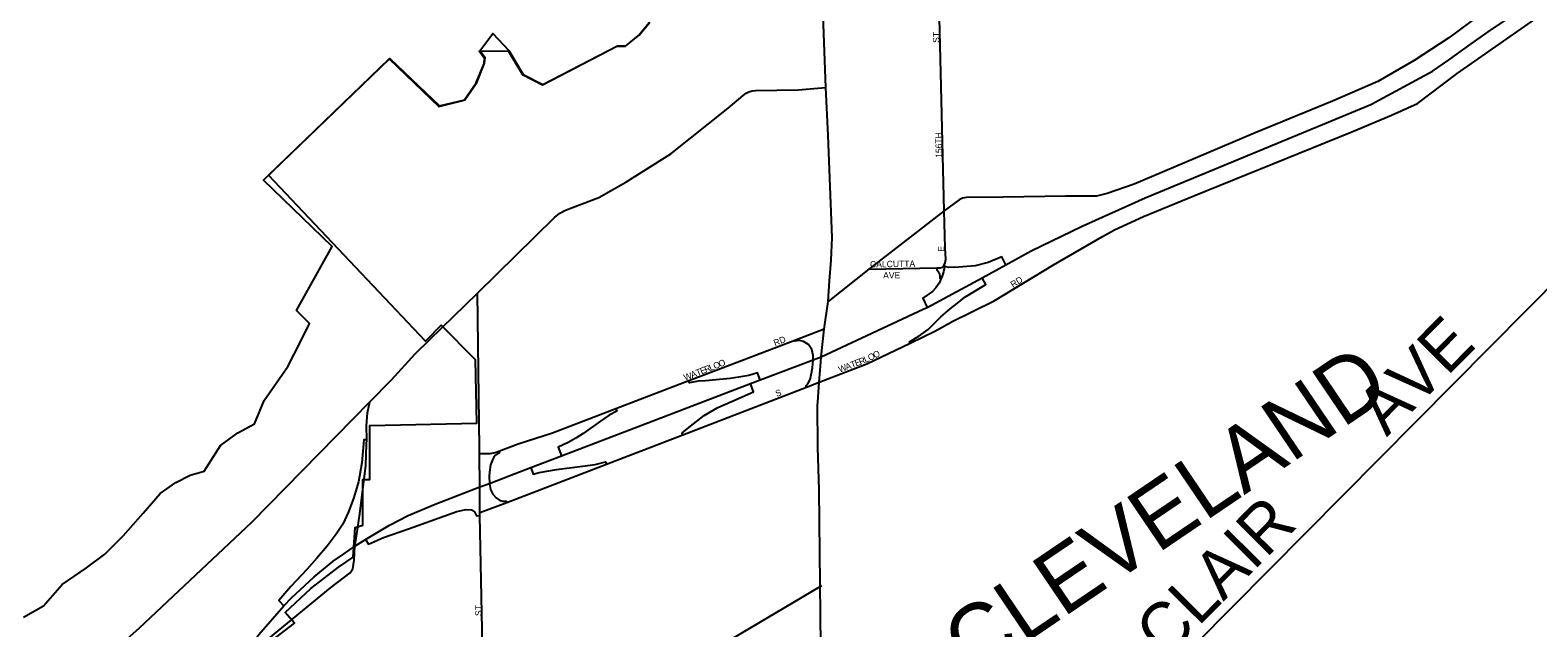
# Model space of a CAD drawing. Extents: x 2139079 to 2262683, y 1235796 to 1334992.
# Drawn here: x 2215487 to 2227269, y 1298965 to 1303635 of the extents above; entities that cross this region are included whole.
import ezdxf

# ---------------------------------------------------------------- set-up
doc = ezdxf.new("R2010")
doc.units = 0
for name, color, linetype in [('GM_X_City_Street', 7, 'Continuous'), ('GM_X_City_Street_Text', 7, 'Continuous'), ('GM_X_Interchange_Ramps', 7, 'Continuous'), ('GM_X_Interstate_Route', 7, 'Continuous'), ('GM_X_Major_Lake', 7, 'Continuous'), ('GM_X_Rail_Line', 7, 'Continuous'), ('GM_X_State_Route', 7, 'Continuous')]:
    doc.layers.add(name, color=color, linetype=linetype)

msp = doc.modelspace()

# ---------------------------------------------------------------- linework, layer by layer
at = {"layer": 'GM_X_City_Street'}
for points in [[(2222628, 1301794), (2222637, 1301818), (2222642, 1301847), (2222639, 1301934), (2222631, 1302223), (2222576, 1304490), (2222574, 1305072)], [(2227721, 1304477), (2227713, 1304469), (2227476, 1304236), (2226827, 1303763), (2226574, 1303576), (2226302, 1303399), (2226018, 1303234), (2225664, 1303080), (2225061, 1302833), (2224423, 1302561), (2224116, 1302431), (2223903, 1302360), (2223821, 1302337), (2223611, 1302337)], [(2224582, 1302340), (2225815, 1302840), (2226127, 1302972), (2226328, 1303063), (2226639, 1303296), (2227803, 1304111), (2228191, 1304381)], [(2224021, 1298258), (2229194, 1303478)], [(2221735, 1301676), (2221747, 1301837), (2221756, 1302015), (2221724, 1302813), (2221705, 1303186)], [(2223611, 1302337), (2223578, 1302337), (2223092, 1302331), (2222804, 1302328), (2222772, 1302323), (2222748, 1302309), (2222631, 1302223), (2222042, 1301769), (2221723, 1301514)], [(2223868, 1302023), (2223961, 1302076), (2224189, 1302180), (2224582, 1302340)], [(2222688, 1301355), (2223020, 1301520), (2223484, 1301801), (2223868, 1302023)], [(2222042, 1301769), (2222572, 1301778), (2222599, 1301779), (2222616, 1301784), (2222628, 1301794)], [(2218999, 1300368), (2218984, 1301579)], [(2221666, 1301040), (2221669, 1301083), (2221692, 1301299), (2221723, 1301514), (2221735, 1301676)], [(2221653, 1300884), (2222025, 1301029), (2222363, 1301189), (2222558, 1301282), (2222685, 1301353), (2222688, 1301355)], [(2221509, 1301229), (2221463, 1301211), (2220848, 1300976), (2220634, 1300894), (2220065, 1300677), (2219568, 1300487), (2219302, 1300401), (2219149, 1300344), (2219121, 1300333), (2219080, 1300324), (2219000, 1300324)], [(2221692, 1301299), (2221509, 1301229)], [(2221642, 1300728), (2221653, 1300884), (2221666, 1301040)], [(2219213, 1299945), (2219990, 1300244), (2220588, 1300474), (2221554, 1300846), (2221653, 1300884)], [(2210766, 1293922), (2211801, 1293964), (2212305, 1294027), (2212399, 1294027), (2212467, 1294064), (2212638, 1294239), (2212785, 1294454), (2212887, 1294652), (2212956, 1294842), (2213029, 1295050), (2213142, 1295274), (2213283, 1295420), (2213573, 1295709), (2214318, 1296503), (2214511, 1296741), (2214593, 1296875), (2214794, 1297172), (2214854, 1297277), (2214913, 1297522), (2214973, 1297723), (2215173, 1297924), (2216341, 1298965), (2217219, 1299790), (2218141, 1300730)], [(2221725, 1292831), (2221701, 1295749), (2221700, 1295837), (2221672, 1298336), (2221653, 1300040), (2221643, 1300378), (2221640, 1300704), (2221642, 1300728)], [(2219002, 1299842), (2219002, 1299866), (2219002, 1300066), (2219000, 1300324), (2218999, 1300368)], [(2219002, 1299866), (2219213, 1299945)], [(2219028, 1294314), (2219028, 1294762), (2219026, 1298699), (2219002, 1299842)]]:
    msp.add_lwpolyline(points, dxfattribs=at)
at = {"layer": 'GM_X_Interchange_Ramps'}
for points in [[(2223112, 1301801), (2223081, 1301863), (2222975, 1301821), (2222872, 1301794), (2222745, 1301783), (2222666, 1301782), (2222643, 1301785), (2222628, 1301794)], [(2222363, 1301189), (2222358, 1301199), (2222433, 1301244), (2222506, 1301297), (2222604, 1301395), (2222678, 1301457), (2222733, 1301501), (2222792, 1301549), (2222956, 1301647), (2222928, 1301699)], [(2222628, 1301794), (2222629, 1301771), (2222625, 1301746), (2222612, 1301706), (2222607, 1301694), (2222591, 1301659), (2222566, 1301621), (2222539, 1301594), (2222462, 1301540), (2222496, 1301469)], [(2222572, 1301778), (2222573, 1301764), (2222590, 1301738), (2222596, 1301716), (2222597, 1301698), (2222607, 1301694)], [(2221554, 1300846), (2221550, 1300856), (2221566, 1300878), (2221583, 1300906), (2221591, 1300943), (2221602, 1300998), (2221605, 1301059), (2221607, 1301093), (2221596, 1301141), (2221569, 1301178), (2221531, 1301202), (2221500, 1301210), (2221465, 1301205), (2221463, 1301211)], [(2220588, 1300474), (2220582, 1300489), (2220671, 1300559), (2220754, 1300624), (2220862, 1300686), (2220963, 1300732), (2221141, 1300809), (2221116, 1300873)], [(2221191, 1300902), (2221170, 1300957), (2221103, 1300936), (2221026, 1300923), (2220957, 1300913), (2220766, 1300896), (2220708, 1300892), (2220640, 1300879), (2220634, 1300894)], [(2220065, 1300677), (2220072, 1300658), (2220012, 1300628), (2219945, 1300579), (2219810, 1300484), (2219751, 1300446), (2219691, 1300414), (2219613, 1300378), (2219639, 1300310)], [(2218118, 1300435), (2218096, 1300435), (2218079, 1300255), (2218052, 1300107), (2218016, 1299984), (2217976, 1299871), (2217930, 1299775), (2217878, 1299698), (2217809, 1299604), (2217728, 1299509), (2217649, 1299421), (2217525, 1299288), (2217431, 1299179), (2217470, 1299136)], [(2219149, 1300344), (2219154, 1300332), (2219139, 1300324), (2219124, 1300313), (2219112, 1300299), (2219103, 1300284), (2219094, 1300266), (2219085, 1300240), (2219076, 1300181), (2219075, 1300149), (2219077, 1300094), (2219086, 1300047), (2219103, 1300010), (2219128, 1299982), (2219155, 1299963), (2219181, 1299956), (2219210, 1299954), (2219213, 1299945)], [(2219401, 1300218), (2219418, 1300166), (2219466, 1300180), (2219600, 1300203), (2219803, 1300228), (2219902, 1300241), (2219983, 1300262), (2219990, 1300244)], [(2218109, 1299655), (2218131, 1299619), (2218248, 1299670), (2218445, 1299739), (2218822, 1299874), (2218891, 1299889), (2218936, 1299886), (2218960, 1299872), (2218975, 1299841), (2219002, 1299842)]]:
    msp.add_lwpolyline(points, dxfattribs=at)
at = {"layer": 'GM_X_Interstate_Route'}
for points in [[(2217271, 1298786), (2217552, 1299002), (2217481, 1299084), (2217681, 1299272), (2217816, 1299377), (2217896, 1299439), (2218012, 1299516), (2218026, 1299749), (2218086, 1299768), (2218088, 1300123), (2218143, 1300123), (2218142, 1300546), (2218977, 1300565), (2218968, 1301059), (2218700, 1301330), (2218577, 1301205), (2217351, 1302503), (2218293, 1303411), (2218681, 1303040), (2218879, 1303088), (2218974, 1303224), (2219034, 1303375), (2219038, 1303415), (2218997, 1303471), (2219224, 1303473), (2219336, 1303288), (2219490, 1303207), (2220072, 1303510), (2220139, 1303509), (2220242, 1303593), (2220325, 1303696)], [(2221669, 1301083), (2222467, 1301454), (2222496, 1301469), (2222928, 1301699), (2223112, 1301801), (2223309, 1301911), (2223709, 1302103), (2224201, 1302326), (2225963, 1303055), (2226447, 1303314), (2226572, 1303401), (2226730, 1303516), (2226881, 1303622), (2227040, 1303729)], [(2217937, 1299541), (2218025, 1299602), (2218109, 1299655), (2218296, 1299766), (2218442, 1299843), (2218652, 1299932), (2219002, 1300066), (2219077, 1300094), (2219243, 1300157), (2219401, 1300218), (2219639, 1300310), (2220347, 1300581), (2221116, 1300873), (2221191, 1300902), (2221605, 1301059), (2221669, 1301083)], [(2217135, 1298719), (2217274, 1298914), (2217470, 1299136), (2217530, 1299200), (2217707, 1299364), (2217852, 1299483)], [(2217852, 1299483), (2217854, 1299485), (2217937, 1299541)]]:
    msp.add_lwpolyline(points, dxfattribs=at)
at = {"layer": 'GM_X_Major_Lake'}
msp.add_lwpolyline([(2215435, 1299049), (2215592, 1299137), (2215737, 1299303), (2215928, 1299435), (2216070, 1299541), (2216215, 1299685), (2216371, 1299862), (2216504, 1300016), (2216625, 1300101), (2216737, 1300159), (2216847, 1300188), (2216974, 1300390), (2217111, 1300488), (2217241, 1300558), (2217317, 1300741), (2217501, 1301006), (2217603, 1301206), (2217670, 1301343), (2217568, 1301445), (2217848, 1301944), (2217310, 1302462), (2218298, 1303414), (2218685, 1303043), (2218883, 1303091), (2218978, 1303226), (2219039, 1303378), (2219042, 1303418), (2219001, 1303474), (2219104, 1303609), (2219228, 1303476), (2219341, 1303290), (2219494, 1303210), (2220077, 1303513), (2220143, 1303512), (2220247, 1303595), (2220330, 1303698)], dxfattribs=at)
at = {"layer": 'GM_X_Rail_Line'}
msp.add_lwpolyline([(2218315, 1297299), (2218388, 1297344), (2219079, 1297766), (2220957, 1298872), (2221673, 1299296)], dxfattribs=at)
at = {"layer": 'GM_X_State_Route'}
for points in [[(2218984, 1301579), (2219586, 1302172), (2219626, 1302204), (2219672, 1302228), (2219931, 1302327), (2220142, 1302447), (2220493, 1302668), (2220943, 1303025), (2221060, 1303126), (2221082, 1303142), (2221103, 1303153), (2221129, 1303160), (2221156, 1303163), (2221490, 1303170), (2221705, 1303186), (2221660, 1304389)], [(2218610, 1301217), (2218984, 1301579)], [(2218141, 1300730), (2218311, 1300902), (2218495, 1301106), (2218610, 1301217)], [(2218032, 1299648), (2218063, 1299855), (2218111, 1300234), (2218117, 1300400), (2218118, 1300435), (2218116, 1300544), (2218124, 1300646), (2218141, 1300730)], [(2217135, 1298719), (2217261, 1298782), (2217353, 1298882), (2217835, 1299277), (2217987, 1299396), (2218008, 1299426), (2218020, 1299493), (2218025, 1299602)], [(2218025, 1299602), (2218032, 1299648)]]:
    msp.add_lwpolyline(points, dxfattribs=at)

# ---------------------------------------------------------------- texts
at = {"layer": 'GM_X_City_Street_Text'}
for s, height, rotation, p in [('ST', 50, 90, (2222592, 1303536)), ('156TH', 50, 91.1685, (2222614, 1302638)), ('E', 50, 90, (2222632, 1301904)), ('CALCUTTA', 50, 0.7738, (2222051, 1301781)), ('AVE', 50, 0, (2222153, 1301695)), ('RD', 50, 32.0029, (2223168, 1301621)), ('ST        CLAIR       AVE', 375, 45.1511, (2223121, 1297469)), ('RD', 50, 22.3775, (2221309, 1301165)), ('O', 50, 25.6685, (2222048, 1301050)), ('O', 50, 25.7188, (2222088, 1301069)), ('T', 50, 21.2091, (2220701, 1300932)), ('E', 50, 21.218, (2220734, 1300945)), ('R', 50, 21.1927, (2220767, 1300958)), ('L', 50, 21.2091, (2220804, 1300972)), ('O', 50, 21.2007, (2220837, 1300985)), ('O', 50, 21.2156, (2220878, 1301001)), ('W', 50, 20.9929, (2221815, 1300958)), ('A', 50, 20.9653, (2221868, 1300978)), ('T', 50, 20.9873, (2221909, 1300994)), ('E', 50, 20.9845, (2221942, 1301007)), ('R', 50, 21.3591, (2221975, 1301019)), ('L', 50, 24.186, (2222015, 1301035)), ('W', 50, 19.9716, (2220605, 1300896)), ('A', 50, 21.1151, (2220660, 1300916)), ('S', 50, 20.571, (2221322, 1300769)), ('ST', 50, 90, (2219015, 1299057))]:
    msp.add_text(s, height=height, rotation=rotation, dxfattribs=at).set_placement(p)
at = {"layer": 'GM_X_State_Route'}
msp.add_text('CLEVELAND', height=500, rotation=34.1113, dxfattribs=at).set_placement((2222850, 1298562))

doc.saveas('drawing.dxf')
